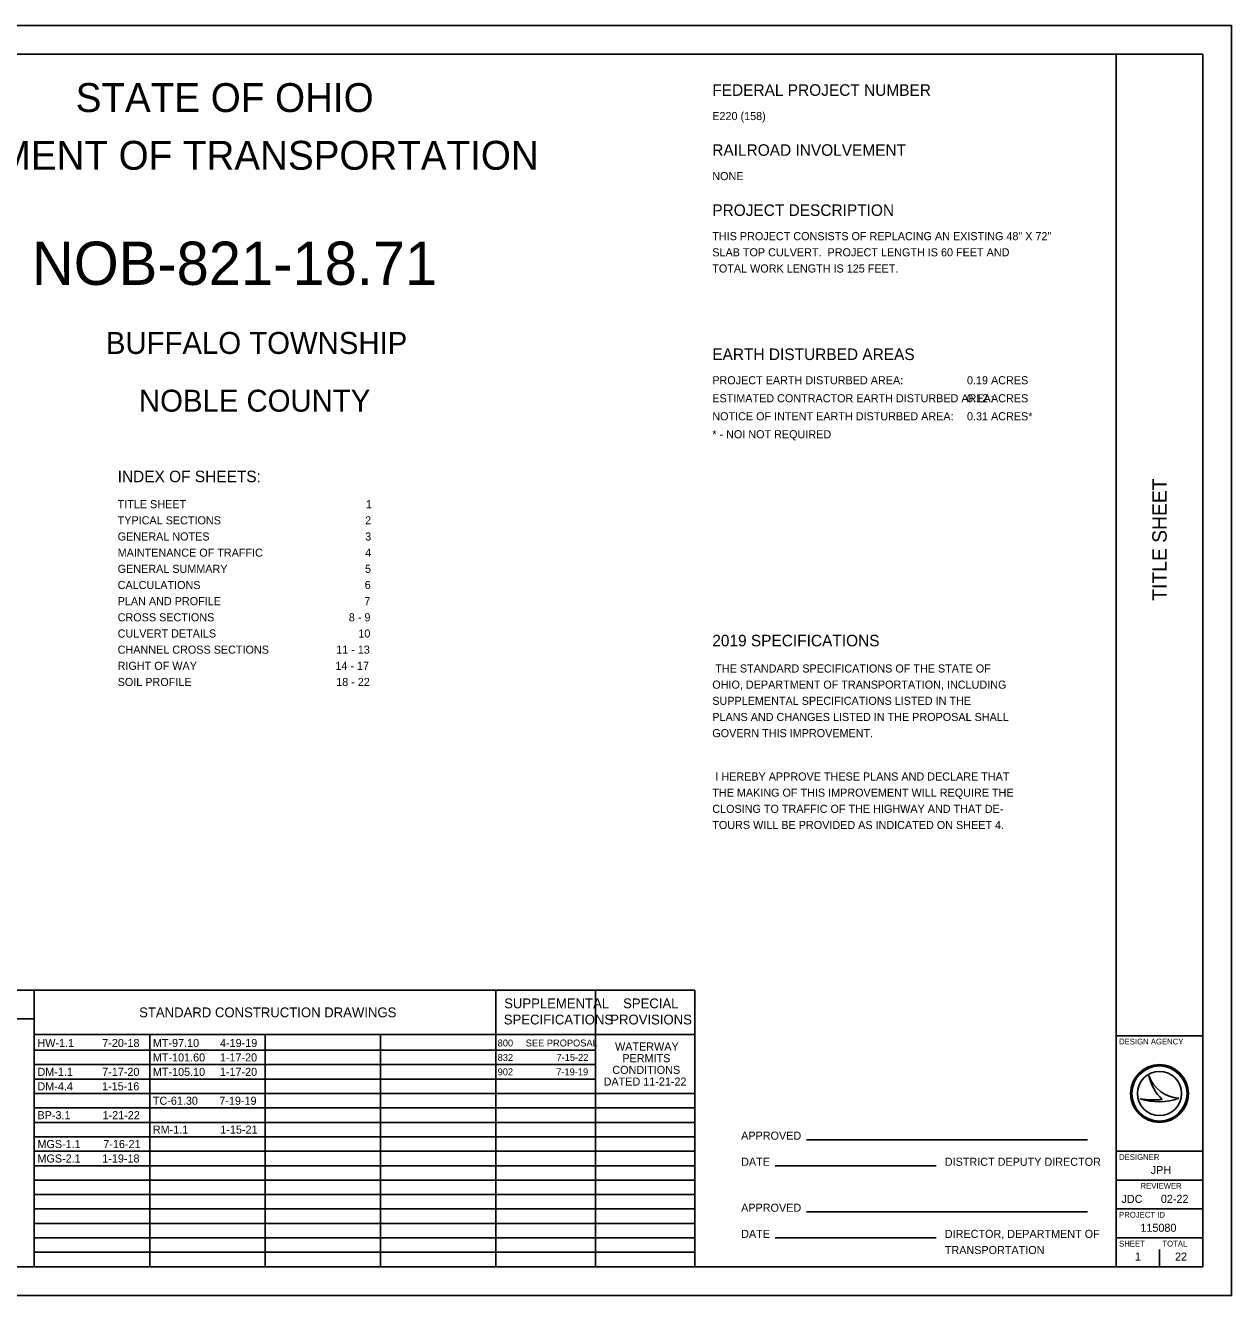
# Model space of a CAD drawing. Extents: x 0 to 34, y 0 to 22.
# Drawn here: x 13.1 to 34, y 0 to 22 of the extents above; entities that cross this region are included whole.
import ezdxf

# ---------------------------------------------------------------- set-up
doc = ezdxf.new("R2010")
doc.units = 0
for name, color, linetype in [('SH_Border', 7, 'Continuous'), ('SH_Cut_Line', 7, 'Continuous'), ('SH_Data', 7, 'Continuous'), ('SH_Text', 7, 'Continuous')]:
    doc.layers.add(name, color=color, linetype=linetype)

msp = doc.modelspace()

# ---------------------------------------------------------------- linework, layer by layer
at = {"layer": 'SH_Border'}
for p, q in [((32, 0.5), (32, 21.5)), ((32, 4.5), (33.5, 4.5)), ((32, 2.5), (33.5, 2.5)), ((32, 2), (33.5, 2)), ((32, 1.5), (33.5, 1.5)), ((32, 1), (33.5, 1))]:
    msp.add_line(p, q, dxfattribs=at)
msp.add_lwpolyline([(1.5, 21.5), (33.5, 21.5), (33.5, 0.5), (1.5, 0.5)], close=True, dxfattribs=at)
at = {"layer": 'SH_Cut_Line'}
msp.add_lwpolyline([(0, 0), (34, 0), (34, 22), (0, 22)], close=True, dxfattribs=at)
at = {"layer": 'SH_Data'}
for p, q in [((25, 9.06), (25, 9.06)), ((8.45, 5.292), (24.7, 5.292)), ((13.25, 0.5), (13.25, 5.292)), ((21.25, 0.5), (21.25, 5.292)), ((22.975, 0.5), (22.975, 5.292)), ((24.7, 0.5), (24.7, 5.292)), ((8.45, 4.792), (13.25, 4.792)), ((13.25, 4.521), (24.7, 4.521)), ((15.25, 0.5), (15.25, 4.521)), ((17.25, 0.5), (17.25, 4.521)), ((19.25, 0.5), (19.25, 4.521)), ((13.25, 4.25), (22.975, 4.25)), ((13.25, 4), (22.975, 4)), ((13.25, 3.75), (22.975, 3.75)), ((32.567, 3.81), (32.567, 3.81)), ((13.25, 3.5), (24.7, 3.5)), ((32.417, 3.41), (32.417, 3.41)), ((32.75, 3.5), (32.75, 3.5)), ((33.087, 3.419), (33.087, 3.419)), ((13.25, 3.25), (24.7, 3.25)), ((13.25, 3), (24.7, 3)), ((13.25, 2.75), (24.7, 2.75)), ((26.635, 2.7), (31.5, 2.7)), ((13.25, 2.5), (24.7, 2.5)), ((13.25, 2.25), (24.7, 2.25)), ((26.091, 2.248), (28.878, 2.248)), ((13.25, 2), (24.7, 2)), ((13.25, 1.75), (24.7, 1.75)), ((13.25, 1.5), (24.7, 1.5)), ((26.635, 1.452), (31.5, 1.452)), ((13.25, 1.25), (24.7, 1.25)), ((13.25, 1), (24.7, 1)), ((26.091, 0.999), (28.878, 0.999)), ((13.25, 0.75), (24.7, 0.75)), ((32.375, 0.675), (32.375, 0.675)), ((32.75, 0.5), (32.75, 0.8))]:
    msp.add_line(p, q, dxfattribs=at)
for radius in [0.5, 0.477, 0.477, 0.382]:
    msp.add_circle((32.75, 3.5), radius, dxfattribs=at)
for centre, radius, start, end in [((33.116, 3.998), 0.58, 198.9257, 198.9319), ((33.347, 3.97), 0.796, 191.6379, 191.6421), ((33.116, 3.998), 0.58, 198.9319, 267.1657), ((33.347, 3.97), 0.796, 191.6421, 226.0947), ((32.739, 4.37), 1.013, 251.4576, 290.0832), ((32.648, 4.654), 1.266, 259.4964, 259.4995), ((32.739, 4.37), 1.013, 251.4527, 251.4576), ((32.648, 4.654), 1.266, 259.4995, 276.6672)]:
    msp.add_arc(centre, radius, start, end, dxfattribs=at)

# ---------------------------------------------------------------- texts
msp.add_text('TITLE SHEET', height=0.25, rotation=90, dxfattribs=at).set_placement((32.875, 12.035))
for s, height, p in [(' I HEREBY APPROVE THESE PLANS AND DECLARE THAT', 0.14, (25, 8.921)), ('THE MAKING OF THIS IMPROVEMENT WILL REQUIRE THE', 0.14, (25, 8.641)), ('CLOSING TO TRAFFIC OF THE HIGHWAY AND THAT DE-', 0.14, (25, 8.361)), ('TOURS WILL BE PROVIDED AS INDICATED ON SHEET 4.', 0.14, (25, 8.081)), ('DESIGN AGENCY', 0.1, (32.05, 4.35)), ('DESIGNER', 0.1, (32.05, 2.35)), ('JPH', 0.14, (32.598, 2.105)), ('REVIEWER', 0.1, (32.422, 1.85)), ('JDC', 0.14, (32.091, 1.605)), ('02-22', 0.14, (32.774, 1.605)), ('PROJECT ID', 0.1, (32.05, 1.35)), ('115080', 0.14, (32.419, 1.105)), ('SHEET', 0.1, (32.05, 0.85)), ('TOTAL', 0.1, (32.8, 0.85)), ('1', 0.14, (32.325, 0.605)), ('22', 0.14, (33.019, 0.605))]:
    msp.add_text(s, height=height, dxfattribs=at).set_placement(p)
at = {"layer": 'SH_Text'}
for s, height, p in [('STATE OF OHIO', 0.5, (13.968, 20.5)), ('FEDERAL PROJECT NUMBER', 0.2, (25, 20.78)), ('E220 (158)', 0.14, (25, 20.36)), ('DEPARTMENT OF TRANSPORTATION', 0.5, (9.92, 19.5)), ('RAILROAD INVOLVEMENT', 0.2, (25, 19.741)), ('NONE', 0.14, (25, 19.32)), ('PROJECT DESCRIPTION', 0.2, (25, 18.7)), ('NOB-821-18.71', 0.75, (13.209, 17.505)), ('THIS PROJECT CONSISTS OF REPLACING AN EXISTING 48" X 72"', 0.14, (25, 18.28)), ('SLAB TOP CULVERT.  PROJECT LENGTH IS 60 FEET AND', 0.14, (25, 18)), ('TOTAL WORK LENGTH IS 125 FEET.', 0.14, (25, 17.72)), ('BUFFALO TOWNSHIP', 0.38, (14.491, 16.31)), ('EARTH DISTURBED AREAS', 0.2, (25, 16.204)), ('PROJECT EARTH DISTURBED AREA:', 0.14, (25, 15.784)), ('0.19 ACRES', 0.14, (29.414, 15.784)), ('NOBLE COUNTY', 0.38, (15.064, 15.31)), ('ESTIMATED CONTRACTOR EARTH DISTURBED AREA:', 0.14, (25, 15.472)), ('0.12 ACRES', 0.14, (29.414, 15.472)), ('NOTICE OF INTENT EARTH DISTURBED AREA:', 0.14, (25, 15.16)), ('0.31 ACRES*', 0.14, (29.414, 15.16)), ('* - NOI NOT REQUIRED', 0.14, (25, 14.849)), ('INDEX OF SHEETS:', 0.2, (14.695, 14.088)), ('TITLE SHEET', 0.14, (14.695, 13.638)), ('1', 0.14, (18.997, 13.638)), ('TYPICAL SECTIONS', 0.14, (14.695, 13.358)), ('2', 0.14, (18.984, 13.358)), ('GENERAL NOTES', 0.14, (14.695, 13.078)), ('3', 0.14, (18.985, 13.078)), ('MAINTENANCE OF TRAFFIC', 0.14, (14.695, 12.798)), ('4', 0.14, (18.985, 12.798)), ('GENERAL SUMMARY', 0.14, (14.695, 12.518)), ('5', 0.14, (18.982, 12.518)), ('CALCULATIONS', 0.14, (14.695, 12.238)), ('6', 0.14, (18.976, 12.238)), ('PLAN AND PROFILE', 0.14, (14.695, 11.958)), ('7', 0.14, (18.97, 11.958)), ('CROSS SECTIONS', 0.14, (14.695, 11.678)), ('8 - 9', 0.14, (18.701, 11.678)), ('CULVERT DETAILS', 0.14, (14.695, 11.398)), ('10', 0.14, (18.866, 11.398)), ('2019 SPECIFICATIONS', 0.2, (25, 11.245)), ('CHANNEL CROSS SECTIONS', 0.14, (14.695, 11.118)), ('11 - 13', 0.14, (18.482, 11.118)), ('RIGHT OF WAY', 0.14, (14.695, 10.838)), ('14 - 17', 0.14, (18.468, 10.838)), (' THE STANDARD SPECIFICATIONS OF THE STATE OF', 0.14, (25, 10.792)), ('SOIL PROFILE', 0.14, (14.695, 10.558)), ('18 - 22', 0.14, (18.482, 10.558)), ('OHIO, DEPARTMENT OF TRANSPORTATION, INCLUDING', 0.14, (25, 10.512)), ('SUPPLEMENTAL SPECIFICATIONS LISTED IN THE', 0.14, (25, 10.232)), ('PLANS AND CHANGES LISTED IN THE PROPOSAL SHALL', 0.14, (25, 9.952)), ('GOVERN THIS IMPROVEMENT.', 0.14, (25, 9.672)), ('SUPPLEMENTAL', 0.17, (21.393, 4.976)), ('SPECIAL', 0.17, (23.454, 4.976)), ('STANDARD CONSTRUCTION DRAWINGS', 0.17, (15.067, 4.821)), ('SPECIFICATIONS', 0.17, (21.387, 4.696)), ('PROVISIONS', 0.17, (23.232, 4.696)), ('HW-1.1', 0.14, (13.305, 4.305)), ('7-20-18', 0.14, (14.428, 4.305)), ('MT-97.10', 0.14, (15.305, 4.305)), ('4-19-19', 0.14, (16.469, 4.305)), ('800', 0.12, (21.28, 4.315)), ('SEE PROPOSAL', 0.12, (21.767, 4.315)), ('MT-101.60', 0.14, (15.305, 4.055)), ('1-17-20', 0.14, (16.466, 4.055)), ('832', 0.12, (21.28, 4.065)), ('7-15-22', 0.12, (22.3, 4.065)), ('WATERWAY', 0.14, (23.315, 4.244)), ('PERMITS', 0.14, (23.441, 4.042)), ('CONDITIONS', 0.14, (23.268, 3.839)), ('DM-1.1', 0.14, (13.305, 3.805)), ('7-17-20', 0.14, (14.427, 3.805)), ('MT-105.10', 0.14, (15.305, 3.805)), ('1-17-20', 0.14, (16.466, 3.805)), ('902', 0.12, (21.28, 3.815)), ('7-19-19', 0.12, (22.296, 3.815)), ('DATED 11-21-22', 0.14, (23.117, 3.637)), ('DM-4.4', 0.14, (13.305, 3.555)), ('1-15-16', 0.14, (14.425, 3.555)), ('TC-61.30', 0.14, (15.305, 3.305)), ('7-19-19', 0.14, (16.457, 3.305)), ('BP-3.1', 0.14, (13.305, 3.055)), ('1-21-22', 0.14, (14.433, 3.055)), ('RM-1.1', 0.14, (15.305, 2.805)), ('1-15-21', 0.14, (16.474, 2.805)), ('MGS-1.1', 0.14, (13.305, 2.555)), ('7-16-21', 0.14, (14.446, 2.555)), ('APPROVED', 0.14, (25.5, 2.7)), ('MGS-2.1', 0.14, (13.305, 2.305)), ('1-19-18', 0.14, (14.428, 2.305)), ('DATE', 0.14, (25.5, 2.248)), ('DISTRICT DEPUTY DIRECTOR', 0.14, (29.03, 2.248)), ('APPROVED', 0.14, (25.5, 1.452)), ('DATE', 0.14, (25.5, 0.999)), ('DIRECTOR, DEPARTMENT OF', 0.14, (29.03, 0.999)), ('TRANSPORTATION', 0.14, (29.03, 0.719))]:
    msp.add_text(s, height=height, dxfattribs=at).set_placement(p)

doc.saveas('drawing.dxf')
